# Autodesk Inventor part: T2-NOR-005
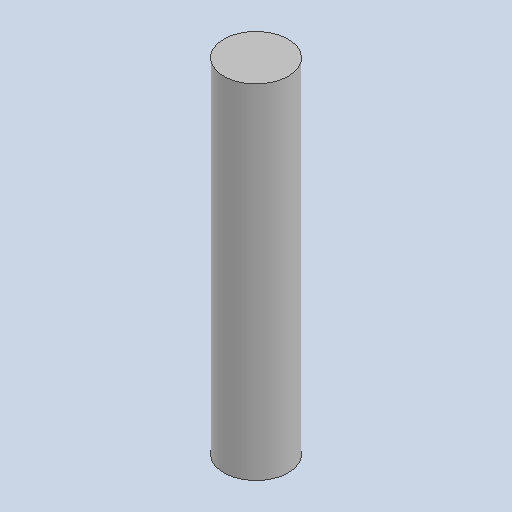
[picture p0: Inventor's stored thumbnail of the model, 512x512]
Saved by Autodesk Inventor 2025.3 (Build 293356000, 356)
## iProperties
Created: 2026-10
Part Number: T2-NOR-005
Material: Genérico
Document SubType Name: Modeling
Designer: Luis MuÃ±oz
Density: 1 g/cm^3
Appearance: Valor por defecto
Project: TESIS 2 - Plataforma mecatrÃ³nica preventiva desacoplada
Description: Pasador cilíndrico Ø3 × 16 mm
Author: Luis M
Title: Pasador cilÃ­ndrico Ã˜3 Ã— 16 mm
Revision Number: 00
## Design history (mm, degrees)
sketch "Boceto1"
  geometry: C1 r 1.5 at (0, 0); 1 further point
  constraints: 1 centre point, 1 coincident
  dimensions: "d0" = 3 diameter of C1
extrude "Extrusión1" new body sketch "Boceto1" distance "d1" = 16; taper "d2" = 0 deg
node "Sólido1"
